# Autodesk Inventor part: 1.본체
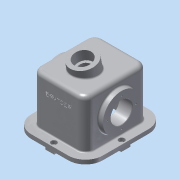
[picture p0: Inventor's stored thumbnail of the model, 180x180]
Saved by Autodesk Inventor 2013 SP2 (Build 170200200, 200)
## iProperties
Created: 2014-11
Part Number: 1.본체
Material: 알루미늄 6061
Document SubType Name: Modeling
Designer: dgall
Density: 2.71 g/cm^3
Mass: 2882.1 g
Surface Area: 2079.78 cm^2
Volume: 1063.5 cm^3
Author: dgall
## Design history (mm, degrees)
sketch "스케치1"
  geometry: L1 (-87, 98)-(87, 98); L2 (87, 98)-(87, -98); L3 (87, -98)-(-87, -98); L4 (-87, -98)-(-87, 98); 3 further points
  constraints: 8 end point, 2 midpoint, 2 parallel, 1 horizontal, 1 horizontal alignment, 1 perpendicular, 1 vertical alignment
  dimensions: "d0" = 196 distance of L1.end L2.end; "d2" = 174 distance of L2.end L3.end
extrude "돌출1" new body sketch "스케치1" distance "d3" = 10; taper "d4" = 0 deg
sketch "스케치2"
  geometry: L1 (65, -0.8)-(65, 118); L2 (65, 118)-(-65, 118); L3 (-65, 118)-(-65, -0.8); L4 (-87, 0)-(87, 0) reference; L5 (-65, -0.8)-(65, -0.8); 3 further points
  constraints: 8 end point, 2 midpoint, 2 perpendicular, 1 parallel, 1 vertical, 1 vertical alignment
  dimensions: "d5" = 130 distance of L1.end L2.end; "d7" = 118 distance between parallel lines of L2 L4
extrude "돌출2" join sketch "스케치2" stored distance "d8" = 152; taper "d9" = 0 deg
node "작업 평면2"
sketch "스케치4"
  geometry: L1 (98, 0)-(-98, 0) reference; L2 (98, -10)-(-98, -10) reference; C1 r 45.5 at (0, 58); 2 further points
  constraints: 2 vertical alignment, 1 centre point, 1 midpoint
  dimensions: "d11" = 68 distance from line of C1.centre L2; "d12" = 91 diameter of C1
extrude "돌출3" join sketch "스케치4" stored distance "d13" = 152; taper "d14" = 0 deg
node "작업 평면3"
sketch "스케치5"
  geometry: L1 (-98, -10)-(98, -10) reference; L2 (-98, 0)-(98, 0) reference; L3 (-66, -10)-(-66, 108); L4 (-66, 108)-(66, 108); L5 (66, 108)-(66, -10); L6 (76, 0)-(76, 118) reference; L7 (76, 118)-(-76, 118) reference; 3 further points
  constraints: 6 end point, 2 midpoint, 2 perpendicular, 2 point on line, 1 horizontal, 1 parallel, 1 vertical alignment
  dimensions: "d16" = 10 distance between parallel lines of L6 L5; "d17" = 10 distance between parallel lines of L7 L4
extrude "돌출4" cut sketch "스케치5" stored distance "d18" = 110; taper "d19" = 0 deg
sketch "스케치6"
  geometry: L1 (55, 108)-(55, -10) reference; L2 (-55, -10)-(55, -10) reference; L3 (55, 103.5)-(45, 93.5); L4 (45, 93.5)-(45, 58); L5 (45, 58)-(55, 58); 1 further point
  constraints: 6 end point, 2 point on line, 1 horizontal, 1 perpendicular
  dimensions: "d31" = 68 distance between parallel lines of L5 L2; "d32" = 71 diameter of L3.end L5; "d33" = 91 diameter of L3.start L5; "d34" = 10 horizontal distance of L3.start L3.end
revolve "회전1" sketch "스케치6" stored, may be unused: angle "d35" = 90 deg
sketch "스케치7"
  geometry: C1 r 45.5 at (0, 0) reference; C2 r 26 at (0, 0); 1 further point
  constraints: 1 centre point, 1 coincident
  dimensions: "d36" = 52 diameter of C2
extrude "돌출5" cut sketch "스케치7" stored distance "d38" = 110; taper "d39" = 0 deg
node "작업 평면4"
node "작업 평면6"
  node "작업 평면5"
sketch "스케치8"
  geometry: L1 (0, -45.5)-(0, 45.5) reference; L2 (164, -107.917)-(-10, -107.917) reference; C1 r 31 at (77, 0); 3 further points
  constraints: 2 midpoint, 1 centre point, 1 coincident, 1 horizontal alignment, 1 vertical alignment
  dimensions: "d42" = 62 diameter of C1
extrude "돌출6" join sketch "스케치8" stored distance "d44" = 110; taper "d45" = 0 deg
sketch "스케치9"
  geometry: C1 r 31 at (0, 0) reference; C2 r 21 at (0, 0)
  constraints: 1 centre point, 1 coincident
  dimensions: "d46" = 42 diameter of C2
extrude "돌출7" cut sketch "스케치9" distance "d48" = 25; taper "d49" = 0 deg
sketch "스케치10"
  geometry: C1 r 21 at (0, 0) reference; C2 r 15 at (0, 0)
  constraints: 1 centre point, 1 coincident
  dimensions: "d50" = 30 diameter of C2
extrude "돌출8" cut sketch "스케치10" stored distance "d52" = 25; taper "d53" = 0 deg
node "작업 평면7"
sketch "스케치11"
  geometry: C1 r 26 at (0, 0) reference; C2 r 45.5 at (0, 0) reference; A1 r 35 centre (0, 0) between (35, 0) and (0, 35); 3 further points
  constraints: 4 point on circle, 2 horizontal alignment, 2 vertical alignment, 1 centre point, 1 coincident
  dimensions: "d54" = 70 diameter of A1
hole "구멍1" sketch "스케치11" at (35, 0), (0, 35), (0, -35), (-35, 0) diameter "d56" = 3.242; stored, may be unused: countersink angle "d60" = 90 deg, drill point angle "d62" = 118 deg; dims "d57" = 13, "d58" = 4, "d59" = 2, "d61" = 16
node "작업 평면8"
sketch "스케치12"
  geometry: L1 (87, 98)-(-87, 98) reference; L2 (87, -98)-(87, 98) reference; L3 (11, 98)-(11, 78); L4 (11, 78)-(-11, 78); L5 (-11, 78)-(-11, 98); 2 further points
  constraints: 6 end point, 2 perpendicular, 2 point on line, 1 midpoint, 1 parallel, 1 vertical alignment
  dimensions: "d64" = 20 distance of L4.end L5.end; "d66" = 22 distance of L3.end L4.end
extrude "돌출9" join sketch "스케치12" distance "d67" = 5; taper "d68" = 0 deg
sketch "스케치13"
  geometry: L1 (-87, 98)-(-87, -98) reference; L2 (87, -98)-(87, 98) reference; L3 (55, -66)-(-55, -66) reference; L4 (87, -11)-(67, -11); L5 (67, -11)-(67, 11); L6 (67, 11)-(87, 11); L7 (-87, -11)-(-67, -11); L8 (-67, -11)-(-67, 11); L9 (-67, 11)-(-87, 11); 3 further points
  constraints: 12 end point, 4 perpendicular, 4 point on line, 2 horizontal alignment, 2 midpoint, 1 horizontal, 1 parallel
  dimensions: "d70" = 22 distance of L4.end L5.end; "d72" = 20 distance of L5.end L6.end; "d73" = 22 distance of L7.end L8.end; "d74" = 20 distance of L8.end L9.end
extrude "돌출10" join sketch "스케치13" distance "d75" = 5; taper "d76" = 0 deg
fillet "모깎기2" dims "d78" = 20
fillet "모깎기3" dims "d79" = 10
fillet "모깎기4" dims "d80" = 42
fillet "모깎기5" dims "d81" = 3
fillet "모깎기6" dims "d82" = 3
fillet "모깎기7" dims "d83" = 3
fillet "모깎기8" dims "d84" = 3
chamfer "모따기1" distance "d85" = 1; stored, may be unused: second distance "d86" = 2, angle "d87" = 45 deg
node "작업 평면9"
sketch "스케치17"
  geometry: L1 (-45, 98)-(45, 98) reference; L2 (-87, -56)-(-87, 56) reference; L3 (45, -98)-(-45, -98) reference; L4 (87, 56)-(87, -56) reference; C1 r 7 at (0, 88); C2 r 7 at (0, -88); C3 r 7 at (77, 0); C4 r 7 at (-77, 0); 1 further point
  constraints: 4 centre point, 3 equal radius, 2 horizontal alignment, 2 vertical alignment
  dimensions: "d88" = 14 diameter of C3; "d90" = 10 distance from line of L4 C3.centre; "d91" = 10 distance from line of L2 C4.centre; "d92" = 10 distance from line of L3 C2.centre; "d93" = 10 distance from line of L1 C1.centre
extrude "돌출11" cut sketch "스케치17" distance "d94" = 8.6; taper "d95" = 0 deg
sketch "스케치18"
  geometry: C1 r 7 at (0, 0) reference; C2 r 4.5 at (0, 0); C3 r 7 at (0, -176) reference; C4 r 4.5 at (0, -176); C5 r 7 at (77, -88) reference; C6 r 7 at (-77, -88) reference; C7 r 4.5 at (-77, -88); C8 r 4.5 at (77, -88); 1 further point
  constraints: 4 centre point, 4 coincident, 3 equal radius
  dimensions: "d96" = 9 diameter of C2
extrude "돌출12" cut sketch "스케치18" stored distance "d98" = 8.6; taper "d99" = 0 deg
fillet "모깎기9" dims "d100" = 10
fillet "모깎기10" dims "d101" = 3
sketch "스케치19"
  geometry: L1 (45, 118)-(-45, 118) reference; L2 (45, -10)-(11, -10) reference; 3 further points
  constraints: 1 midpoint, 1 vertical alignment, 1 other
  dimensions: "d102" = 92 distance from line of point (0, 82) L2
feature "엠보싱1" sketch "스케치19" dims "d103" = 1, "d104" = 0
fillet "모깎기11" dims "d105" = 0.3
node "솔리드1"
mirror "대칭1"
mirror "대칭2"
mirror "대칭3"
mirror "대칭4"
mirror "대칭5"
node "작업축1"
node "작업 평면10"
other parameters: "d10" = -77, "d15" = 0, "d40" = -78 deg, "d41" = 86
